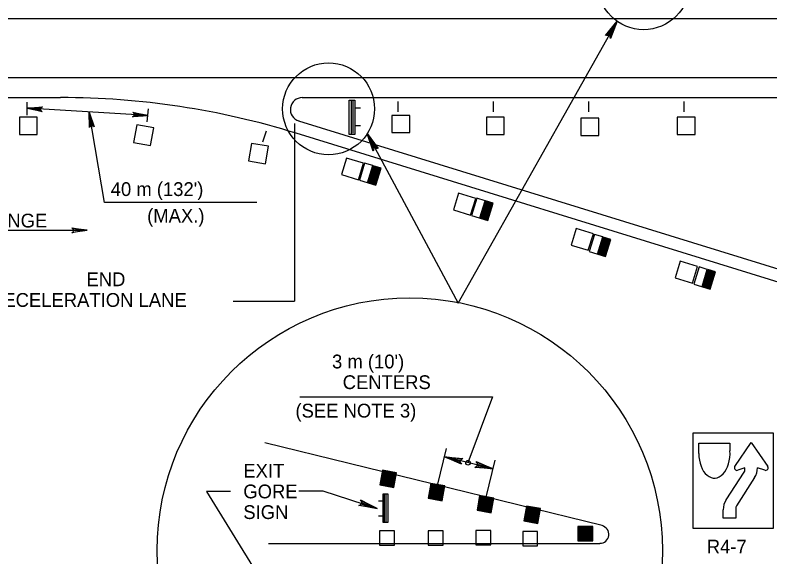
# Model space of a CAD drawing. Extents: x 640253 to 641999, y 298458 to 299646.
# Drawn here: x 641380.3 to 641544.6, y 299301.1 to 299419 of the extents above; entities that cross this region are included whole.
import ezdxf

# ---------------------------------------------------------------- set-up
doc = ezdxf.new("R2010")
doc.units = 0
doc.layers.add('2', color=7, linetype='Continuous')

msp = doc.modelspace()

# ---------------------------------------------------------------- linework, layer by layer
at = {"layer": '2'}
for p, q in [((641249.69, 299418.29), (641619.6, 299418.29)), ((641476.68, 299356.36), (641511.29, 299417.7)), ((641249.69, 299405.41), (641548.4, 299405.41)), ((641249.69, 299401.07), (641390.19, 299401.07)), ((641382.87, 299397.25), (641382.87, 299400.1)), ((641442.79, 299401.07), (641619.17, 299401.07)), ((641453.42, 299400.37), (641453.42, 299393.22)), ((641453.82, 299400.27), (641453.82, 299393.32)), ((641463.65, 299398), (641463.65, 299400.2)), ((641484.41, 299398), (641484.41, 299400.2)), ((641505.15, 299398), (641505.15, 299400.2)), ((641525.91, 299398), (641525.91, 299400.2)), ((641409.18, 299397.15), (641382.87, 299398.74)), ((641409.01, 299395.83), (641409.32, 299398.64)), ((641454.22, 299398.87), (641455.47, 299398.87)), ((641441.09, 299395.45), (641441.09, 299356.79)), ((641554.57, 299361.2), (641442.03, 299395.98)), ((641434.91, 299393.76), (641434.16, 299391.35)), ((641454.22, 299395.02), (641455.47, 299395.02)), ((641556.75, 299357.7), (641441.45, 299393.33)), ((641456.93, 299393.23), (641476.68, 299356.36)), ((641356.59, 299372.2), (641395.96, 299372.2)), ((641508.04, 299307.94), (641434.6, 299325.94)), ((641472.23, 299316.68), (641474.19, 299324.75)), ((641529.09, 299323.64), (641529.09, 299325.88)), ((641529.09, 299325.88), (641535.85, 299325.88)), ((641529.09, 299325.88), (641535.85, 299325.88)), ((641529.09, 299323.64), (641529.09, 299325.88)), ((641535.85, 299325.88), (641535.85, 299324.2)), ((641535.85, 299325.88), (641535.85, 299324.2)), ((641536.93, 299320.81), (641540.52, 299326.05)), ((641540.52, 299326.05), (641544.12, 299320.81)), ((641484.34, 299320.29), (641473.74, 299322.88)), ((641535.85, 299324.2), (641535.88, 299324.2)), ((641482.83, 299314.1), (641484.79, 299322.16)), ((641535.04, 299313.57), (641539, 299319.58)), ((641536.97, 299320.86), (641536.93, 299320.81)), ((641536.97, 299320.86), (641536.93, 299320.81)), ((641536.97, 299320.86), (641536.93, 299320.81)), ((641539.15, 299320.52), (641537.59, 299320.01)), ((641539.15, 299320.12), (641539.15, 299320.52)), ((641543.49, 299320), (641541.88, 299320.52)), ((641541.25, 299318.38), (641537.31, 299312.22)), ((641421.94, 299315.4), (641446.55, 299275.57)), ((641427.15, 299315.4), (641421.94, 299315.4)), ((641460.71, 299308.85), (641460.71, 299314.64)), ((641461.05, 299308.77), (641461.05, 299314.73)), ((641460.38, 299313.23), (641459.34, 299313.23)), ((641534.4, 299309.58), (641534.4, 299311.38)), ((641537.14, 299311.7), (641537.14, 299309.58)), ((641460.38, 299310.02), (641459.34, 299310.02)), ((641537.14, 299309.58), (641534.4, 299309.58)), ((641435.45, 299304.08), (641507.56, 299304.08))]:
    msp.add_line(p, q, dxfattribs=at)
for points in [[(641508.99, 299414.65), (641509.3, 299414.64), (641511.29, 299417.7), (641508.99, 299414.65), (641508.75, 299414.57), (641511.29, 299417.7), (641509.64, 299414.45), (641509.81, 299414.2), (641511.29, 299417.7), (641509.86, 299413.94), (641509.81, 299414.2)], [(641386, 299398.14), (641385.89, 299398.37), (641382.87, 299398.74), (641386, 299398.14), (641386.14, 299397.99), (641382.87, 299398.74), (641385.91, 299398.7), (641386.03, 299398.92), (641382.87, 299398.74), (641386.21, 299399.05), (641386.03, 299398.92)], [(641396.55, 299394.74), (641396.76, 299394.9), (641396.43, 299397.92), (641396.55, 299394.74), (641396.45, 299394.57), (641396.43, 299397.92), (641397.07, 299394.95), (641397.32, 299394.88), (641396.43, 299397.92), (641397.49, 299394.74), (641397.32, 299394.88)], [(641432.86, 299378.27), (641399.7, 299378.27), (641396.43, 299397.92)], [(641406.06, 299397.77), (641406.17, 299397.54), (641409.18, 299397.15), (641406.06, 299397.77), (641405.91, 299397.92), (641409.18, 299397.15), (641406.14, 299397.21), (641406.02, 299396.99), (641409.18, 299397.15), (641405.84, 299396.87), (641406.02, 299396.99)], [(641458.25, 299389.65), (641458.43, 299389.91), (641456.93, 299393.23), (641458.25, 299389.65), (641458.19, 299389.4), (641456.93, 299393.23), (641458.76, 299390.08), (641459.07, 299390.09), (641456.93, 299393.23), (641459.32, 299389.99), (641459.07, 299390.09)], [(641457.01, 299382.56), (641458.15, 299386.29), (641456.36, 299386.83), (641455.22, 299383.11), (641458.8, 299382.01), (641459.95, 299385.74), (641458.23, 299386.26), (641457.11, 299382.6), (641458.77, 299382.09), (641459.87, 299385.69), (641458.28, 299386.18), (641457.19, 299382.65), (641458.73, 299382.18), (641459.79, 299385.63), (641458.33, 299386.08), (641457.29, 299382.7), (641458.68, 299382.27), (641459.69, 299385.58), (641458.38, 299385.98), (641457.38, 299382.75), (641458.62, 299382.37), (641459.59, 299385.51), (641458.43, 299385.87), (641457.49, 299382.8), (641458.57, 299382.47), (641459.48, 299385.46), (641458.48, 299385.75), (641457.59, 299382.86), (641458.52, 299382.58), (641459.38, 299385.4), (641458.53, 299385.66), (641457.69, 299382.92), (641458.45, 299382.68), (641459.27, 299385.32), (641458.6, 299385.53), (641457.82, 299382.98), (641458.39, 299382.81), (641459.14, 299385.24), (641458.66, 299385.38), (641457.94, 299383.04), (641458.33, 299382.92), (641459.01, 299385.16), (641458.74, 299385.25), (641458.08, 299383.11), (641458.26, 299383.06), (641458.89, 299385.08), (641458.8, 299385.11), (641458.19, 299383.17)], [(641481.41, 299374.89), (641482.56, 299378.62), (641480.76, 299379.16), (641479.62, 299375.44), (641483.2, 299374.34), (641484.35, 299378.07), (641482.64, 299378.59), (641481.51, 299374.93), (641483.17, 299374.42), (641484.27, 299378.02), (641482.68, 299378.51), (641481.6, 299374.98), (641483.13, 299374.51), (641484.19, 299377.96), (641482.73, 299378.41), (641481.69, 299375.03), (641483.08, 299374.6), (641484.09, 299377.91), (641482.78, 299378.31), (641481.79, 299375.08), (641483.03, 299374.7), (641483.99, 299377.85), (641482.83, 299378.2), (641481.89, 299375.13), (641482.97, 299374.8), (641483.88, 299377.79), (641482.88, 299378.08), (641482, 299375.19), (641482.92, 299374.91), (641483.79, 299377.73), (641482.94, 299377.99), (641482.1, 299375.25), (641482.86, 299375.01), (641483.67, 299377.66), (641483, 299377.86), (641482.22, 299375.32), (641482.79, 299375.14), (641483.54, 299377.57), (641483.06, 299377.71), (641482.34, 299375.37), (641482.73, 299375.26), (641483.41, 299377.5), (641483.14, 299377.58), (641482.48, 299375.44), (641482.66, 299375.39), (641483.29, 299377.42), (641483.2, 299377.44), (641482.59, 299375.5)], [(641392.8, 299372.6), (641392.92, 299372.38), (641395.96, 299372.2), (641392.8, 299372.6), (641392.64, 299372.74), (641395.96, 299372.2), (641392.92, 299372.05), (641392.81, 299371.82), (641395.96, 299372.2), (641392.64, 299371.68), (641392.81, 299371.82)], [(641507.02, 299367.02), (641508.17, 299370.75), (641506.38, 299371.29), (641505.23, 299367.57), (641508.81, 299366.47), (641509.96, 299370.2), (641508.25, 299370.72), (641507.12, 299367.06), (641508.78, 299366.55), (641509.88, 299370.15), (641508.29, 299370.64), (641507.21, 299367.11), (641508.74, 299366.64), (641509.8, 299370.09), (641508.34, 299370.54), (641507.3, 299367.16), (641508.69, 299366.73), (641509.7, 299370.04), (641508.39, 299370.44), (641507.4, 299367.21), (641508.64, 299366.83), (641509.6, 299369.97), (641508.44, 299370.33), (641507.5, 299367.26), (641508.58, 299366.93), (641509.49, 299369.92), (641508.49, 299370.21), (641507.61, 299367.32), (641508.53, 299367.04), (641509.4, 299369.86), (641508.55, 299370.12), (641507.71, 299367.38), (641508.47, 299367.14), (641509.28, 299369.78), (641508.61, 299369.99), (641507.83, 299367.45), (641508.4, 299367.27), (641509.15, 299369.7), (641508.67, 299369.84), (641507.95, 299367.5), (641508.34, 299367.38), (641509.03, 299369.62), (641508.75, 299369.71), (641508.09, 299367.57), (641508.27, 299367.52), (641508.9, 299369.55), (641508.81, 299369.57), (641508.2, 299367.63)], [(641529.81, 299359.95), (641530.95, 299363.68), (641529.16, 299364.23), (641528.02, 299360.5), (641531.6, 299359.41), (641532.75, 299363.13), (641531.03, 299363.66), (641529.91, 299360), (641531.57, 299359.49), (641532.67, 299363.08), (641531.08, 299363.57), (641529.99, 299360.05), (641531.53, 299359.58), (641532.59, 299363.03), (641531.13, 299363.47), (641530.09, 299360.1), (641531.48, 299359.67), (641532.49, 299362.97), (641531.18, 299363.38), (641530.18, 299360.15), (641531.42, 299359.77), (641532.39, 299362.91), (641531.23, 299363.26), (641530.29, 299360.2), (641531.37, 299359.86), (641532.28, 299362.85), (641531.28, 299363.15), (641530.39, 299360.25), (641531.32, 299359.98), (641532.18, 299362.79), (641531.33, 299363.05), (641530.49, 299360.32), (641531.25, 299360.08), (641532.07, 299362.72), (641531.4, 299362.92), (641530.62, 299360.38), (641531.19, 299360.21), (641531.94, 299362.64), (641531.46, 299362.78), (641530.74, 299360.44), (641531.13, 299360.32), (641531.81, 299362.56), (641531.54, 299362.65), (641530.88, 299360.51), (641531.06, 299360.45), (641531.69, 299362.48), (641531.6, 299362.51), (641530.99, 299360.56)], [(641427.72, 299356.79), (641441.09, 299356.79)], [(641442.27, 299335.98), (641484.21, 299335.98), (641478.83, 299321.62)], [(641477.3, 299321.52), (641477.23, 299321.82), (641473.74, 299322.88), (641477.3, 299321.52), (641477.45, 299321.32), (641473.74, 299322.88), (641477.32, 299322.19), (641477.51, 299322.43), (641473.74, 299322.88), (641477.75, 299322.55), (641477.51, 299322.43)], [(641480.78, 299321.65), (641480.85, 299321.35), (641484.34, 299320.29), (641480.78, 299321.65), (641480.63, 299321.86), (641484.34, 299320.29), (641480.76, 299320.98), (641480.57, 299320.75), (641484.34, 299320.29), (641480.32, 299320.62), (641480.57, 299320.75)], [(641462.72, 299316.25), (641463.28, 299319.45), (641460.21, 299319.99), (641459.65, 299316.79), (641462.72, 299316.25), (641460.25, 299319.93), (641459.71, 299316.83), (641462.69, 299316.31), (641463.23, 299319.41), (641460.31, 299319.91), (641459.78, 299316.89), (641462.64, 299316.38), (641463.16, 299319.35), (641460.37, 299319.83), (641459.86, 299316.93), (641462.6, 299316.45), (641463.1, 299319.31), (641460.41, 299319.78), (641459.92, 299316.98), (641462.57, 299316.51), (641463.03, 299319.25), (641460.45, 299319.69), (641459.98, 299317.02), (641462.53, 299316.57), (641462.97, 299319.2), (641460.5, 299319.62), (641460.06, 299317.07), (641462.48, 299316.64), (641462.91, 299319.16), (641460.55, 299319.55), (641460.12, 299317.11), (641462.42, 299316.7), (641462.83, 299319.1), (641460.61, 299319.48), (641460.2, 299317.18), (641462.39, 299316.76), (641462.75, 299319.03), (641460.65, 299319.4), (641460.27, 299317.23), (641462.35, 299316.83), (641462.69, 299318.98), (641460.68, 299319.32), (641460.34, 299317.28), (641462.33, 299316.9), (641462.62, 299318.91), (641460.73, 299319.23), (641460.43, 299317.34), (641461.32, 299317.14), (641462.28, 299316.98), (641462.55, 299318.86), (641460.8, 299319.14), (641460.53, 299317.39), (641462.23, 299317.06), (641462.48, 299318.8), (641460.85, 299319.06), (641460.62, 299317.46), (641462.18, 299317.16), (641462.4, 299318.7), (641460.94, 299318.94), (641460.73, 299317.56), (641462.09, 299317.27), (641462.3, 299318.6), (641461, 299318.8), (641460.85, 299317.67), (641462.01, 299317.4), (641462.02, 299317.41), (641462.16, 299318.5), (641461.1, 299318.67), (641460.98, 299317.76), (641461.93, 299317.54), (641462.03, 299318.39), (641461.21, 299318.54), (641461.11, 299317.86), (641461.82, 299317.7), (641461.9, 299318.28), (641461.29, 299318.36), (641461.25, 299317.98), (641461.74, 299317.87), (641461.76, 299318.15), (641461.4, 299318.22), (641461.35, 299318.1), (641461.64, 299318.04)], [(641473.25, 299313.37), (641473.81, 299316.57), (641470.73, 299317.11), (641470.18, 299313.91), (641473.25, 299313.37), (641470.78, 299317.05), (641470.24, 299313.96), (641473.22, 299313.44), (641473.76, 299316.53), (641470.84, 299317.04), (641470.31, 299314.01), (641473.17, 299313.51), (641473.69, 299316.47), (641470.9, 299316.95), (641470.39, 299314.05), (641473.13, 299313.57), (641473.63, 299316.43), (641470.94, 299316.9), (641470.45, 299314.1), (641473.09, 299313.64), (641473.56, 299316.37), (641470.98, 299316.82), (641470.51, 299314.15), (641473.06, 299313.69), (641473.5, 299316.33), (641471.03, 299316.74), (641470.58, 299314.19), (641473.01, 299313.76), (641473.43, 299316.28), (641471.08, 299316.68), (641470.65, 299314.24), (641472.95, 299313.82), (641473.36, 299316.22), (641471.14, 299316.61), (641470.73, 299314.3), (641472.92, 299313.88), (641473.28, 299316.15), (641471.17, 299316.52), (641470.8, 299314.35), (641472.88, 299313.95), (641473.22, 299316.1), (641471.21, 299316.45), (641470.87, 299314.4), (641472.86, 299314.03), (641473.15, 299316.03), (641471.26, 299316.36), (641470.96, 299314.47), (641471.85, 299314.27), (641472.81, 299314.1), (641473.08, 299315.98), (641471.33, 299316.26), (641471.05, 299314.51), (641472.76, 299314.18), (641473.01, 299315.92), (641471.38, 299316.18), (641471.15, 299314.59), (641472.71, 299314.28), (641472.93, 299315.83), (641471.47, 299316.06), (641471.26, 299314.68), (641472.62, 299314.4), (641472.82, 299315.72), (641471.53, 299315.93), (641471.38, 299314.79), (641472.54, 299314.53), (641472.54, 299314.53), (641472.69, 299315.62), (641471.63, 299315.8), (641471.51, 299314.88), (641472.46, 299314.66), (641472.56, 299315.51), (641471.74, 299315.66), (641471.64, 299314.98), (641472.35, 299314.82), (641472.43, 299315.4), (641471.82, 299315.48), (641471.77, 299315.1), (641472.27, 299314.99), (641472.29, 299315.28), (641471.93, 299315.34), (641471.88, 299315.23), (641472.17, 299315.16)], [(641442.03, 299315.49), (641447.23, 299315.49), (641459.05, 299311.68)], [(641455.6, 299313.31), (641455.65, 299313), (641459.05, 299311.68), (641455.6, 299313.31), (641455.47, 299313.52), (641459.05, 299311.68), (641455.53, 299312.64), (641455.32, 299312.42), (641459.05, 299311.68), (641455.07, 299312.31), (641455.32, 299312.42)], [(641483.89, 299310.73), (641484.45, 299313.93), (641481.38, 299314.47), (641480.82, 299311.27), (641483.89, 299310.73), (641481.43, 299314.41), (641480.89, 299311.31), (641483.86, 299310.79), (641484.4, 299313.89), (641481.48, 299314.39), (641480.95, 299311.36), (641483.82, 299310.86), (641484.33, 299313.83), (641481.54, 299314.31), (641481.03, 299311.41), (641483.78, 299310.93), (641484.28, 299313.79), (641481.58, 299314.26), (641481.09, 299311.46), (641483.74, 299310.99), (641484.21, 299313.73), (641481.63, 299314.18), (641481.16, 299311.5), (641483.7, 299311.05), (641484.14, 299313.69), (641481.68, 299314.1), (641481.23, 299311.55), (641483.66, 299311.11), (641484.08, 299313.64), (641481.72, 299314.03), (641481.3, 299311.59), (641483.6, 299311.18), (641484, 299313.58), (641481.79, 299313.97), (641481.37, 299311.66), (641483.57, 299311.24), (641483.93, 299313.51), (641481.82, 299313.88), (641481.44, 299311.71), (641483.52, 299311.31), (641483.87, 299313.45), (641481.86, 299313.8), (641481.52, 299311.76), (641483.5, 299311.38), (641483.8, 299313.39), (641481.91, 299313.71), (641481.6, 299311.82), (641482.5, 299311.63), (641483.46, 299311.45), (641483.72, 299313.34), (641481.97, 299313.62), (641481.7, 299311.87), (641483.41, 299311.54), (641483.65, 299313.28), (641482.02, 299313.54), (641481.8, 299311.94), (641483.35, 299311.64), (641483.58, 299313.18), (641482.11, 299313.42), (641481.9, 299312.04), (641483.26, 299311.75), (641483.47, 299313.08), (641482.18, 299313.29), (641482.03, 299312.15), (641483.19, 299311.88), (641483.19, 299311.89), (641483.34, 299312.98), (641482.28, 299313.15), (641482.15, 299312.24), (641483.1, 299312.02), (641483.2, 299312.87), (641482.39, 299313.02), (641482.28, 299312.34), (641483, 299312.18), (641483.08, 299312.76), (641482.47, 299312.84), (641482.42, 299312.46), (641482.91, 299312.35), (641482.94, 299312.64), (641482.57, 299312.7), (641482.53, 299312.58), (641482.82, 299312.52)], [(641494.09, 299308.44), (641494.65, 299311.64), (641491.58, 299312.18), (641491.02, 299308.98), (641494.09, 299308.44), (641491.62, 299312.11), (641491.08, 299309.02), (641494.06, 299308.5), (641494.6, 299311.6), (641491.68, 299312.11), (641491.15, 299309.07), (641494.01, 299308.58), (641494.53, 299311.54), (641491.74, 299312.02), (641491.23, 299309.12), (641493.98, 299308.64), (641494.48, 299311.49), (641491.78, 299311.97), (641491.29, 299309.17), (641493.94, 299308.7), (641494.41, 299311.44), (641491.82, 299311.88), (641491.36, 299309.21), (641493.9, 299308.76), (641494.34, 299311.39), (641491.87, 299311.81), (641491.43, 299309.26), (641493.85, 299308.83), (641494.28, 299311.35), (641491.92, 299311.74), (641491.49, 299309.3), (641493.8, 299308.89), (641494.2, 299311.29), (641491.98, 299311.67), (641491.57, 299309.36), (641493.77, 299308.95), (641494.12, 299311.22), (641492.02, 299311.59), (641491.64, 299309.42), (641493.72, 299309.02), (641494.06, 299311.16), (641492.06, 299311.52), (641491.71, 299309.47), (641493.7, 299309.09), (641493.99, 299311.1), (641492.11, 299311.42), (641491.8, 299309.53), (641492.69, 299309.33), (641493.66, 299309.16), (641493.92, 299311.05), (641492.17, 299311.33), (641491.9, 299309.58), (641493.61, 299309.25), (641493.85, 299310.99), (641492.22, 299311.25), (641491.99, 299309.65), (641493.55, 299309.35), (641493.78, 299310.89), (641492.31, 299311.13), (641492.1, 299309.75), (641493.46, 299309.46), (641493.67, 299310.79), (641492.38, 299311), (641492.23, 299309.86), (641493.38, 299309.59), (641493.39, 299309.6), (641493.53, 299310.69), (641492.48, 299310.86), (641492.35, 299309.95), (641493.3, 299309.73), (641493.4, 299310.58), (641492.58, 299310.73), (641492.48, 299310.05), (641493.2, 299309.89), (641493.27, 299310.47), (641492.66, 299310.55), (641492.62, 299310.16), (641493.11, 299310.06), (641493.14, 299310.34), (641492.77, 299310.41), (641492.72, 299310.29), (641493.02, 299310.23)], [(641502.75, 299304.61), (641506, 299304.61), (641506, 299307.73), (641502.75, 299307.73), (641502.75, 299304.61), (641505.95, 299307.68), (641502.81, 299307.68), (641502.81, 299304.66), (641505.95, 299304.66), (641505.95, 299307.62), (641502.87, 299307.62), (641502.87, 299304.72), (641505.88, 299304.72), (641505.88, 299307.55), (641502.93, 299307.55), (641502.93, 299304.76), (641505.83, 299304.76), (641505.83, 299307.5), (641502.99, 299307.5), (641502.99, 299304.81), (641505.76, 299304.82), (641505.76, 299307.44), (641503.04, 299307.44), (641503.04, 299304.86), (641505.71, 299304.88), (641505.69, 299307.38), (641503.1, 299307.38), (641503.09, 299304.92), (641505.65, 299304.93), (641505.63, 299307.32), (641503.16, 299307.32), (641503.14, 299304.98), (641505.58, 299305), (641505.58, 299307.25), (641503.23, 299307.26), (641503.2, 299305.02), (641505.49, 299305.06), (641505.5, 299307.2), (641503.3, 299307.2), (641503.26, 299305.08), (641505.43, 299305.11), (641505.43, 299307.15), (641503.36, 299307.14), (641503.33, 299305.11), (641505.36, 299305.17), (641505.35, 299307.09), (641503.43, 299307.06), (641503.39, 299306.14), (641503.39, 299305.17), (641505.29, 299305.23), (641505.27, 299307), (641503.5, 299306.97), (641503.46, 299305.23), (641505.22, 299305.29), (641505.19, 299306.94), (641503.59, 299306.89), (641503.56, 299305.31), (641505.11, 299305.34), (641505.1, 299306.83), (641503.7, 299306.8), (641503.65, 299305.41), (641504.99, 299305.44), (641504.97, 299306.75), (641503.83, 299306.69), (641503.77, 299305.51), (641503.78, 299305.51), (641504.87, 299305.55), (641504.86, 299306.62), (641503.94, 299306.59), (641503.89, 299305.62), (641504.74, 299305.66), (641504.75, 299306.49), (641504.06, 299306.48), (641504.02, 299305.74), (641504.61, 299305.77), (641504.59, 299306.39), (641504.2, 299306.36), (641504.18, 299305.86), (641504.46, 299305.88), (641504.46, 299306.26), (641504.34, 299306.28), (641504.33, 299305.98)]]:
    msp.add_lwpolyline(points, dxfattribs=at)
for points in [[(641454.25, 299400.54), (641454.25, 299393.05), (641453, 299393.05), (641453, 299400.54)], [(641381.21, 299393.05), (641385.11, 299393.05), (641385.11, 299396.8), (641381.21, 299396.8)], [(641462.28, 299393.46), (641466.18, 299393.46), (641466.18, 299397.2), (641462.28, 299397.2)], [(641482.85, 299393.05), (641486.75, 299393.05), (641486.75, 299396.8), (641482.85, 299396.8)], [(641524.39, 299393.05), (641528.29, 299393.05), (641528.29, 299396.8), (641524.39, 299396.8)], [(641409.77, 299390.67), (641410.44, 299394.51), (641406.75, 299395.16), (641406.08, 299391.32)], [(641503.42, 299392.85), (641507.32, 299392.85), (641507.32, 299396.6), (641503.42, 299396.6)], [(641434.77, 299386.64), (641435.44, 299390.48), (641431.75, 299391.12), (641431.08, 299387.28)], [(641456.14, 299386.77), (641452.41, 299387.92), (641451.31, 299384.34), (641455.03, 299383.19)], [(641480.54, 299379.1), (641476.81, 299380.25), (641475.71, 299376.67), (641479.43, 299375.52)], [(641506.15, 299371.43), (641502.42, 299372.58), (641501.32, 299369), (641505.04, 299367.85)], [(641528.79, 299364.31), (641525.07, 299365.46), (641523.96, 299361.88), (641527.69, 299360.73)], [(641545.26, 299328.13), (641545.26, 299307.31), (641527.9, 299307.31), (641527.9, 299328.13)], [(641460.36, 299308.62), (641460.36, 299314.87), (641461.4, 299314.87), (641461.4, 299308.62)], [(641459.61, 299303.68), (641462.86, 299303.68), (641462.86, 299306.8), (641459.61, 299306.8)], [(641470.21, 299303.69), (641473.45, 299303.69), (641473.45, 299306.81), (641470.21, 299306.81)], [(641480.59, 299303.77), (641483.83, 299303.77), (641483.83, 299306.89), (641480.59, 299306.89)], [(641490.76, 299303.58), (641494, 299303.58), (641494, 299306.7), (641490.76, 299306.7)]]:
    msp.add_lwpolyline(points, close=True, dxfattribs=at)
for centre, radius in [((641517.08, 299425.85), 10), ((641448.51, 299398.62), 10), ((641466.18, 299302.5), 55), ((641478.85, 299321.63), 0.5)]:
    msp.add_circle(centre, radius, dxfattribs=at)
for centre, radius, start, end in [((641390.19, 299227.5), 173.57, 72.8261, 90), ((641442.79, 299398.47), 2.6, 90, 252.8274), ((641537.39, 299320.51), 0.547, 140.3028, 290.6097), ((641538.17, 299320.1), 0.976, 326.6894, 0), ((641537.96, 299320.5), 3.91, 327.3665, 0), ((641543.64, 299320.51), 0.547, 247.919, 41.2726), ((641538.31, 299311.43), 3.91, 146.6949, 180.6095), ((641538.12, 299311.7), 0.976, 147.4332, 180), ((641507.56, 299306.04), 1.95, 270, 76.217)]:
    msp.add_arc(centre, radius, start, end, dxfattribs=at)
msp.add_ellipse((641532.49, 299323.64), major_axis=(0, -5.37), ratio=0.633721, start_param=4.712389, end_param=7.959212, dxfattribs=at)
msp.add_ellipse((641532.49, 299323.64), major_axis=(0, -5.37), ratio=0.633721, start_param=4.712389, end_param=7.959212, dxfattribs=at)
msp.add_ellipse((641532.49, 299323.64), major_axis=(0, -5.37), ratio=0.633721, start_param=4.712389, end_param=7.959212, dxfattribs=at)
msp.add_ellipse((641532.49, 299323.64), major_axis=(0, -5.37), ratio=0.633721, start_param=4.712389, end_param=7.959212, dxfattribs=at)
msp.add_ellipse((641532.49, 299323.64), major_axis=(0, -5.37), ratio=0.633721, start_param=4.712389, end_param=7.959212, dxfattribs=at)
msp.add_ellipse((641532.49, 299323.64), major_axis=(0, -5.37), ratio=0.633721, start_param=4.712389, end_param=7.959212, dxfattribs=at)

# ---------------------------------------------------------------- texts
for s, p in [("40 m (132')", (641401.09, 299379.66)), ('INTERCHANGE', (641358.08, 299372.81)), ('(MAX.)', (641409.02, 299373.87)), ('END', (641395.81, 299360.04)), ('DECELERATION LANE', (641374.82, 299355.54)), ("3 m (10')", (641449.26, 299342.15)), ('CENTERS', (641451.58, 299337.65)), ('  (SEE NOTE 3)', (641439.07, 299331.46)), ('EXIT', (641429.95, 299318.38)), ('GORE', (641429.95, 299313.88)), ('SIGN', (641429.95, 299309.38)), ('R4-7', (641530.83, 299301.88))]:
    msp.add_text(s, height=3, dxfattribs=at).set_placement(p)

doc.saveas('drawing.dxf')
